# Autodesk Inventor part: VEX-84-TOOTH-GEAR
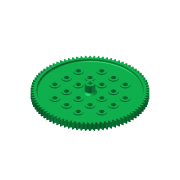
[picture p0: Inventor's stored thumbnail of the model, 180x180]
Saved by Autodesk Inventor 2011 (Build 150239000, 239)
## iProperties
Created: 2007-12
Part Number: VEX-84-TOOTH-GEAR
Document SubType Name: Modeling
Density: 1 g/cm^3
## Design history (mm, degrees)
feature "Base1"
body "Solid1"
